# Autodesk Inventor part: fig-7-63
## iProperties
Shininess: 64.0
Length Units: 11269
Angle Units: 11279
Time Units: 11290
Mass Units: 11283
Length Display Precision: 3
Angle Display Precision: 2
Compacted: True
Part Number: fig-7-63
Document SubType Name: Modeling
Created: 2002-12
Designer: deepak
Density: 1 g/cm^3
Density: 0.0
Volumn: 0.0
Area: 0.0
PropertySet Name: Model Information
Control State: 0
Master: False
Checked Out: False
Author: deepak
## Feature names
1. Extrusion1
2. Split1
